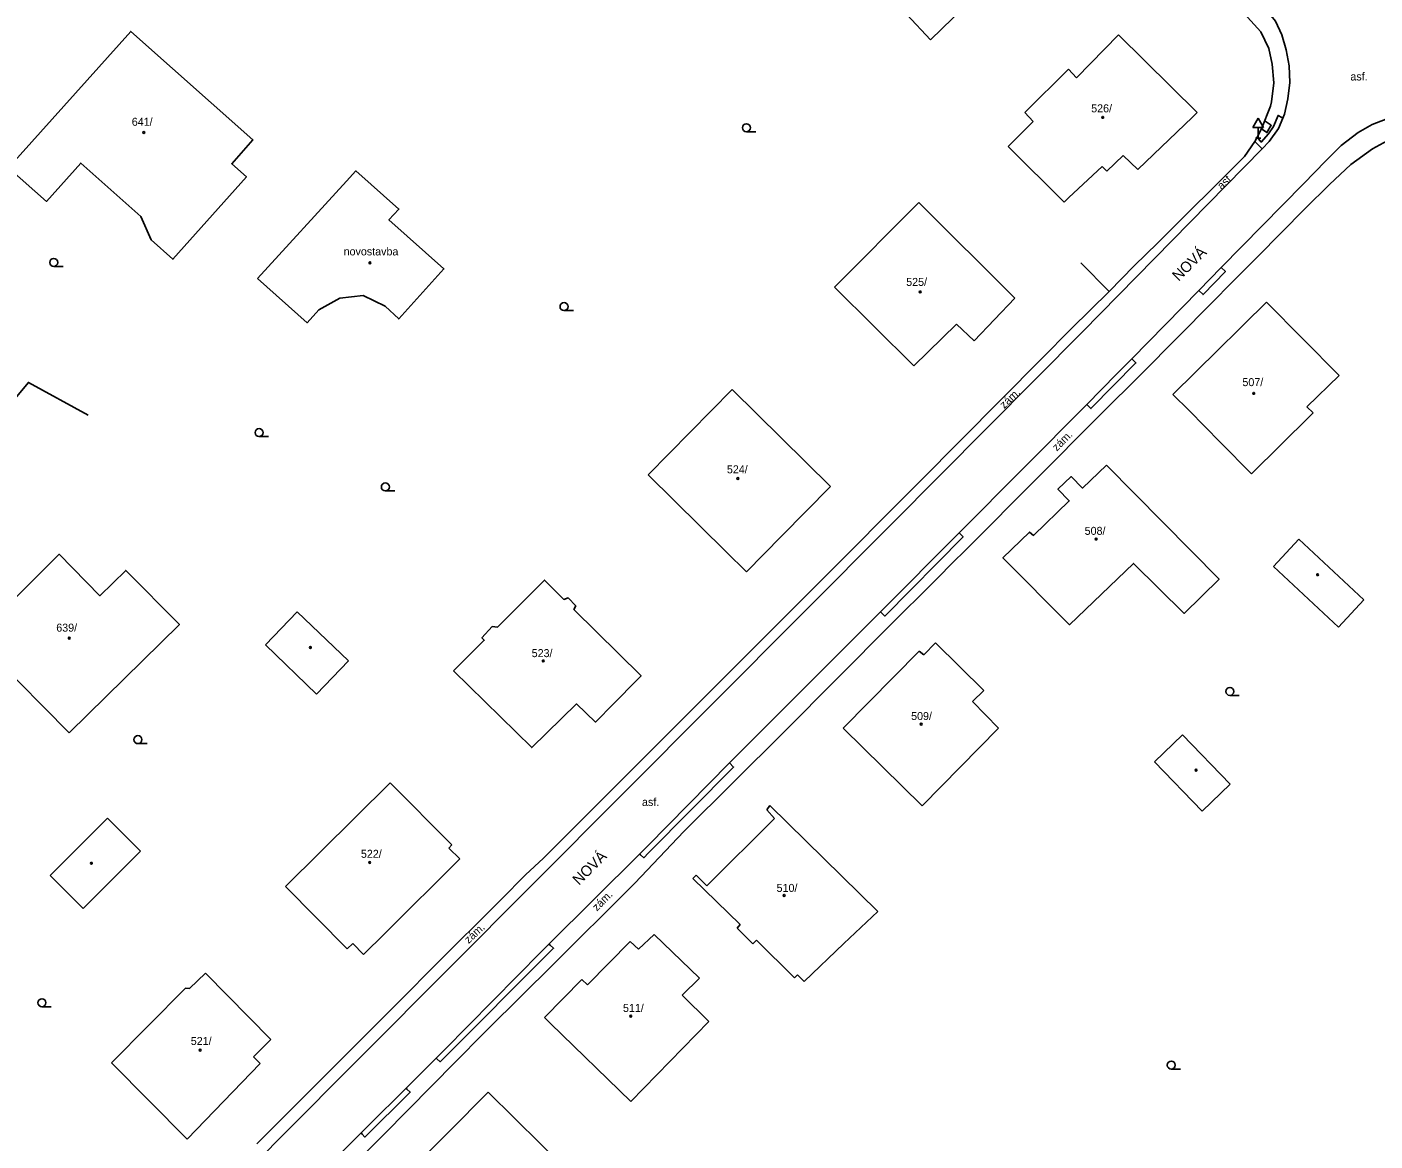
# Model space of a CAD drawing. Extents: x -737488 to -734267, y -1145775 to -1142573.
# Drawn here: x -736592 to -736465.6, y -1144304.9 to -1144200.4 of the extents above; entities that cross this region are included whole.
import ezdxf

# ---------------------------------------------------------------- set-up
doc = ezdxf.new("R2010")
doc.units = 0
for name, color, linetype in [('Vrstva 1', 7, 'Continuous'), ('Vrstva 10', 7, 'Continuous'), ('Vrstva 13', 7, 'Continuous'), ('Vrstva 14', 7, 'Continuous'), ('Vrstva 3', 7, 'Continuous'), ('Vrstva 4', 7, 'Continuous'), ('Vrstva 5', 7, 'Continuous'), ('Vrstva 6', 7, 'Continuous'), ('Vrstva 8', 7, 'Continuous'), ('Vrstva 9', 7, 'Continuous')]:
    doc.layers.add(name, color=color, linetype=linetype)

# ---------------------------------------------------------------- blocks, each defined once
blk = doc.blocks.new('3.040')
at = {"layer": 'Vrstva 1'}
blk.add_line((0, -0.75), (1.75, -0.75), dxfattribs=at)
blk.add_circle((0, 0), 0.75, dxfattribs=at)
blk = doc.blocks.new('4.020')
at = {"layer": 'Vrstva 1'}
blk.add_circle((0, 0), 0.175, dxfattribs=at)
blk = doc.blocks.new('5.270')
at = {"layer": 'Vrstva 1'}
for p, q in [((0, 3.732), (-1, 2)), ((0, 3.732), (1, 2)), ((-1, 2), (1, 2)), ((-0.5, 0), (0.5, 0)), ((0, 0), (0, 2))]:
    blk.add_line(p, q, dxfattribs=at)

msp = doc.modelspace()

# ---------------------------------------------------------------- linework, layer by layer
at = {"layer": 'Vrstva 10'}
for points in [[(-736569.58, -1144306.02), (-736568.51, -1144304.92), (-736544.53, -1144280.81), (-736510.86, -1144247.01), (-736493.03, -1144229.04), (-736476.18, -1144211.88), (-736475.51, -1144211.2), (-736474.66, -1144209.98), (-736474.24, -1144208.99), (-736474.08, -1144208.62), (-736473.78, -1144207.19), (-736473.58, -1144205.66), (-736473.65, -1144204.09), (-736473.93, -1144202.59), (-736474.33, -1144201.18), (-736474.93, -1144199.91), (-736475.73, -1144198.9), (-736476.44, -1144198.24), (-736477.53, -1144197.31), (-736478.84, -1144196.47), (-736482.87, -1144194.17)], [(-736463.99, -1144208.86), (-736465.87, -1144209.59), (-736467.18, -1144210.35), (-736468.78, -1144211.55), (-736470.21, -1144213), (-736472.3, -1144215.15), (-736480.01, -1144223.01), (-736482.11, -1144225.16), (-736488.4, -1144231.57), (-736489.82, -1144233), (-736492.62, -1144235.84), (-736504.6, -1144247.89), (-736511.95, -1144255.31), (-736526.13, -1144269.47), (-736533.8, -1144277.27), (-736534.56, -1144278.02), (-736543.04, -1144286.48), (-736543.73, -1144287.17), (-736552.87, -1144296.41), (-736553.61, -1144297.15), (-736556.44, -1144299.97), (-736559.96, -1144303.48), (-736560.66, -1144304.18), (-736564.18, -1144307.7)], [(-736476.66, -1144210.79), (-736476.26, -1144211.24), (-736475.57, -1144210.45), (-736475.13, -1144209.77), (-736474.69, -1144208.74), (-736474.34, -1144208.93), (-736474.24, -1144208.99)], [(-736475.9, -1144209.28), (-736475.33, -1144209.66), (-736475.73, -1144210.35), (-736476.24, -1144210.01)], [(-736476.86, -1144211.17), (-736476.27, -1144211.79), (-736476.18, -1144211.88)], [(-736482.11, -1144225.16), (-736481.72, -1144225.55), (-736479.62, -1144223.39), (-736480.01, -1144223.01)], [(-736492.62, -1144235.84), (-736492.23, -1144236.23), (-736488.01, -1144231.96), (-736488.4, -1144231.57)], [(-736592.95, -1144235.12), (-736591.84, -1144233.78), (-736586.24, -1144236.86)], [(-736511.95, -1144255.31), (-736511.56, -1144255.7), (-736504.21, -1144248.28), (-736504.6, -1144247.89)], [(-736534.56, -1144278.02), (-736534.47, -1144278.1), (-736534.16, -1144278.37), (-736533.72, -1144277.92), (-736525.74, -1144269.86), (-736526.13, -1144269.47)], [(-736553.61, -1144297.15), (-736553.54, -1144297.22), (-736553.24, -1144297.5), (-736542.61, -1144286.85), (-736542.93, -1144286.57), (-736543.04, -1144286.48)], [(-736560.66, -1144304.18), (-736560.54, -1144304.3), (-736560.29, -1144304.56), (-736556.05, -1144300.34), (-736556.35, -1144300.06), (-736556.44, -1144299.97)]]:
    msp.add_lwpolyline(points, dxfattribs=at)
at = {"layer": 'Vrstva 4'}
for points in [[(-736593.7, -1144213.67), (-736582.24, -1144200.86), (-736570.79, -1144211.03), (-736572.78, -1144213.27), (-736571.41, -1144214.51), (-736578.3, -1144222.23), (-736580.34, -1144220.41), (-736581.31, -1144218.21), (-736586.93, -1144213.21), (-736590.14, -1144216.81), (-736593.7, -1144213.67)], [(-736588.01, -1144266.66), (-736595.16, -1144259.45), (-736595, -1144255.91), (-736588.96, -1144249.9), (-736585.15, -1144253.79), (-736582.71, -1144251.42), (-736577.69, -1144256.48), (-736588.01, -1144266.66)]]:
    msp.add_lwpolyline(points, dxfattribs=at)
at = {"layer": 'Vrstva 5'}
for points in [[(-736499.97, -1144194.52), (-736507.28, -1144201.65)], [(-736507.28, -1144201.65), (-736509.5, -1144199.27)], [(-736493.6, -1144205.21), (-736489.64, -1144201.19)], [(-736489.64, -1144201.19), (-736482.28, -1144208.47)], [(-736498.44, -1144208.46), (-736494.34, -1144204.39)], [(-736494.34, -1144204.39), (-736493.6, -1144205.21)], [(-736497.65, -1144209.3), (-736498.44, -1144208.46)], [(-736482.72, -1144208.89), (-736487.83, -1144213.8)], [(-736482.28, -1144208.47), (-736482.72, -1144208.89)], [(-736499.99, -1144211.66), (-736497.65, -1144209.3)], [(-736494.73, -1144216.86), (-736499.99, -1144211.66)], [(-736489.22, -1144212.5), (-736490.75, -1144213.96)], [(-736487.83, -1144213.8), (-736489.22, -1144212.5)], [(-736570.37, -1144224.02), (-736562.03, -1144214.91), (-736561.16, -1144213.94), (-736557.1, -1144217.52), (-736558.04, -1144218.53), (-736552.89, -1144223.14), (-736557.13, -1144227.83), (-736558.41, -1144226.62), (-736560.46, -1144225.64), (-736562.65, -1144225.89), (-736564.6, -1144226.96), (-736565.71, -1144228.18), (-736570.37, -1144224.02)], [(-736491.19, -1144213.53), (-736494.29, -1144216.44)], [(-736490.75, -1144213.96), (-736491.19, -1144213.53)], [(-736494.29, -1144216.44), (-736494.73, -1144216.86)], [(-736516.26, -1144224.84), (-736508.37, -1144216.92)], [(-736508.37, -1144216.92), (-736499.37, -1144225.89)], [(-736508.84, -1144232.24), (-736516.26, -1144224.84)], [(-736499.37, -1144225.89), (-736503.18, -1144229.89)], [(-736475.78, -1144226.25), (-736477.91, -1144228.36)], [(-736468.97, -1144233.12), (-736475.78, -1144226.25)], [(-736504.82, -1144228.32), (-736508.84, -1144232.24)], [(-736503.18, -1144229.89), (-736504.82, -1144228.32)], [(-736478.37, -1144228.81), (-736480.26, -1144230.68)], [(-736477.91, -1144228.36), (-736478.37, -1144228.81)], [(-736480.26, -1144230.68), (-736484.54, -1144234.9)], [(-736472, -1144236.08), (-736468.97, -1144233.12)], [(-736533.75, -1144242.45), (-736525.86, -1144234.45)], [(-736525.86, -1144234.45), (-736516.64, -1144243.55)], [(-736484.54, -1144234.9), (-736483.03, -1144236.43)], [(-736483.03, -1144236.43), (-736480.08, -1144239.41)], [(-736471.39, -1144236.63), (-736472, -1144236.08)], [(-736471.69, -1144236.92), (-736471.39, -1144236.63)], [(-736477.18, -1144242.35), (-736471.69, -1144236.92)], [(-736480.08, -1144239.41), (-736477.18, -1144242.35)], [(-736490.77, -1144241.54), (-736480.22, -1144252.24), (-736483.48, -1144255.45), (-736488.25, -1144250.76), (-736494.24, -1144256.52), (-736500.49, -1144250.23), (-736497.99, -1144247.82), (-736497.63, -1144248.13), (-736494.27, -1144244.9), (-736495.32, -1144243.81), (-736494.09, -1144242.61), (-736493.03, -1144243.7), (-736490.77, -1144241.54)], [(-736526.44, -1144249.66), (-736533.75, -1144242.45)], [(-736516.64, -1144243.55), (-736521.23, -1144248.2)], [(-736521.23, -1144248.2), (-736524.53, -1144251.55)], [(-736475.13, -1144251.05), (-736472.74, -1144248.48)], [(-736472.74, -1144248.48), (-736466.64, -1144254.18)], [(-736524.53, -1144251.55), (-736526.44, -1144249.66)], [(-736469.03, -1144256.74), (-736475.13, -1144251.05)], [(-736552, -1144260.85), (-736544.66, -1144268.03), (-736540.46, -1144263.94), (-736538.69, -1144265.64), (-736538.31, -1144265.26), (-736537.33, -1144264.27), (-736534.41, -1144261.31), (-736540.7, -1144255.07), (-736540.53, -1144254.74), (-736541.25, -1144254), (-736541.64, -1144254.14), (-736543.46, -1144252.33), (-736547.87, -1144256.73), (-736548.35, -1144256.69), (-736549.32, -1144257.74), (-736549.11, -1144257.97), (-736552, -1144260.85)], [(-736466.64, -1144254.18), (-736469.03, -1144256.74)], [(-736566.64, -1144255.29), (-736569.63, -1144258.41)], [(-736561.83, -1144259.89), (-736566.64, -1144255.29)], [(-736569.63, -1144258.41), (-736564.82, -1144263.01)], [(-736508.32, -1144258.98), (-736515.45, -1144266.22)], [(-736507.91, -1144259.34), (-736508.32, -1144258.98)], [(-736506.81, -1144258.22), (-736507.91, -1144259.34)], [(-736502.27, -1144262.67), (-736506.81, -1144258.22)], [(-736564.82, -1144263.01), (-736561.83, -1144259.89)], [(-736503.35, -1144263.72), (-736502.27, -1144262.67)], [(-736500.9, -1144266.22), (-736503.35, -1144263.72)], [(-736515.45, -1144266.22), (-736508.04, -1144273.49)], [(-736508.04, -1144273.49), (-736500.9, -1144266.22)], [(-736483.64, -1144266.84), (-736486.26, -1144269.38)], [(-736479.17, -1144271.45), (-736483.64, -1144266.84)], [(-736486.26, -1144269.38), (-736481.79, -1144273.99)], [(-736567.74, -1144281.06), (-736557.92, -1144271.34)], [(-736557.92, -1144271.34), (-736552.14, -1144277.17)], [(-736481.79, -1144273.99), (-736479.17, -1144271.45)], [(-736522.33, -1144273.47), (-736522.63, -1144273.88)], [(-736522.63, -1144273.88), (-736521.91, -1144274.68)], [(-736512.2, -1144283.4), (-736522.33, -1144273.47)], [(-736589.81, -1144280.03), (-736584.44, -1144274.66)], [(-736584.44, -1144274.66), (-736581.34, -1144277.76)], [(-736521.91, -1144274.68), (-736528.25, -1144280.99)], [(-736581.34, -1144277.76), (-736586.71, -1144283.13)], [(-736552.14, -1144277.17), (-736552.44, -1144277.48)], [(-736552.44, -1144277.48), (-736551.39, -1144278.46)], [(-736551.39, -1144278.46), (-736558.42, -1144285.46)], [(-736586.71, -1144283.13), (-736589.81, -1144280.03)], [(-736529.24, -1144279.99), (-736529.54, -1144280.31)], [(-736529.54, -1144280.31), (-736525.12, -1144284.63)], [(-736528.25, -1144280.99), (-736529.24, -1144279.99)], [(-736561.97, -1144286.9), (-736567.74, -1144281.06)], [(-736515.4, -1144286.42), (-736512.2, -1144283.4)], [(-736525.12, -1144284.63), (-736525.41, -1144284.97)], [(-736558.42, -1144285.46), (-736560.42, -1144287.45)], [(-736534.66, -1144286.95), (-736533.18, -1144285.57)], [(-736533.18, -1144285.57), (-736528.94, -1144289.67)], [(-736525.41, -1144284.97), (-736523.92, -1144286.43)], [(-736561.43, -1144286.4), (-736561.97, -1144286.9)], [(-736560.42, -1144287.45), (-736561.43, -1144286.4)], [(-736539.42, -1144290.3), (-736535.43, -1144286.23)], [(-736535.43, -1144286.23), (-736534.66, -1144286.95)], [(-736523.92, -1144286.43), (-736523.6, -1144286.11)], [(-736523.6, -1144286.11), (-736520.02, -1144289.63)], [(-736519.11, -1144289.97), (-736515.4, -1144286.42)], [(-736575.24, -1144289.2), (-736576.75, -1144290.64)], [(-736569.1, -1144295.4), (-736575.24, -1144289.2)], [(-736543.46, -1144293.35), (-736539.97, -1144289.78)], [(-736539.97, -1144289.78), (-736539.42, -1144290.3)], [(-736528.94, -1144289.67), (-736530.54, -1144291.26)], [(-736520.02, -1144289.63), (-736519.73, -1144289.36)], [(-736519.73, -1144289.36), (-736519.11, -1144289.97)], [(-736577.13, -1144290.59), (-736584.06, -1144297.6)], [(-736576.75, -1144290.64), (-736577.13, -1144290.59)], [(-736530.54, -1144291.26), (-736528.06, -1144293.74)], [(-736542.89, -1144293.91), (-736543.46, -1144293.35)], [(-736535.37, -1144301.22), (-736542.89, -1144293.91)], [(-736528.06, -1144293.74), (-736535.37, -1144301.22)], [(-736570.73, -1144297.03), (-736569.1, -1144295.4)], [(-736570.1, -1144297.67), (-736570.73, -1144297.03)], [(-736584.06, -1144297.6), (-736576.97, -1144304.76)], [(-736576.97, -1144304.76), (-736570.1, -1144297.67)], [(-736556.07, -1144307.75), (-736548.75, -1144300.35)], [(-736548.75, -1144300.35), (-736541.34, -1144307.68)]]:
    msp.add_lwpolyline(points, dxfattribs=at)
at = {"layer": 'Vrstva 9'}
for points in [[(-736475.23, -1144203.94), (-736475.55, -1144202.47), (-736476.29, -1144200.91), (-736477.55, -1144199.53), (-736478.22, -1144198.88), (-736479.58, -1144198.09)], [(-736477.82, -1144212.6), (-736476.86, -1144211.17), (-736476.66, -1144210.79), (-736476.24, -1144210.01), (-736475.41, -1144207.88), (-736475.3, -1144207.46), (-736475.1, -1144205.68), (-736475.23, -1144203.94)], [(-736461.57, -1144210.4), (-736462.9, -1144210.65), (-736464.47, -1144211.12), (-736465.82, -1144211.88), (-736467.87, -1144213.34)], [(-736485.96, -1144220.7), (-736477.82, -1144212.6)], [(-736467.87, -1144213.34), (-736469.88, -1144215.21)], [(-736469.88, -1144215.21), (-736472.15, -1144217.48)], [(-736472.15, -1144217.48), (-736476.62, -1144222.01)], [(-736485.96, -1144220.7), (-736488.17, -1144222.85)], [(-736493.17, -1144222.56), (-736490.52, -1144225.24)], [(-736476.62, -1144222.01), (-736479.04, -1144224.45)], [(-736490.52, -1144225.24), (-736488.17, -1144222.85)], [(-736494.04, -1144228.72), (-736490.52, -1144225.24)], [(-736479.04, -1144224.45), (-736480.83, -1144226.27)], [(-736480.83, -1144226.27), (-736487.47, -1144232.95)], [(-736494.04, -1144228.72), (-736496.9, -1144231.61)], [(-736508.2, -1144243), (-736496.9, -1144231.61)], [(-736487.47, -1144232.95), (-736491.41, -1144236.85)], [(-736491.41, -1144236.85), (-736503.66, -1144249.17)], [(-736511.6, -1144246.39), (-736508.2, -1144243)], [(-736511.6, -1144246.39), (-736514.51, -1144249.35)], [(-736525.87, -1144260.71), (-736514.51, -1144249.35)], [(-736503.66, -1144249.17), (-736505.54, -1144251.04)], [(-736506.24, -1144251.76), (-736507.08, -1144252.6)], [(-736505.54, -1144251.04), (-736506.24, -1144251.76)], [(-736507.08, -1144252.6), (-736510.92, -1144256.42)], [(-736510.92, -1144256.42), (-736521.04, -1144266.63)], [(-736528.82, -1144263.69), (-736525.87, -1144260.71)], [(-736528.82, -1144263.69), (-736532.15, -1144266.99)], [(-736543.55, -1144278.4), (-736532.15, -1144266.99)], [(-736521.04, -1144266.63), (-736530.39, -1144275.91)], [(-736530.39, -1144275.91), (-736535, -1144280.76)], [(-736543.55, -1144278.4), (-736545.24, -1144279.98)], [(-736545.24, -1144279.98), (-736547.53, -1144282.27)], [(-736535, -1144280.76), (-736543.02, -1144288.75)], [(-736553.86, -1144288.59), (-736547.53, -1144282.27)], [(-736553.86, -1144288.59), (-736556.72, -1144291.49)], [(-736543.02, -1144288.75), (-736545.27, -1144290.99)], [(-736545.27, -1144290.99), (-736549.15, -1144294.83)], [(-736561.27, -1144296.03), (-736556.72, -1144291.49)], [(-736549.15, -1144294.83), (-736551.79, -1144297.52)], [(-736570.44, -1144305.2), (-736561.27, -1144296.03)], [(-736551.79, -1144297.52), (-736556.26, -1144302.03)], [(-736556.26, -1144302.03), (-736558.51, -1144304.31)], [(-736558.51, -1144304.31), (-736563.14, -1144308.96)]]:
    msp.add_lwpolyline(points, dxfattribs=at)

# ---------------------------------------------------------------- block references
at = {"layer": 'Vrstva 3', "xscale": 0.5, "yscale": 0.5}
for p in [(-736524.53, -1144209.89), (-736589.47, -1144222.53), (-736541.63, -1144226.67), (-736570.22, -1144238.49), (-736558.38, -1144243.59), (-736479.21, -1144262.77), (-736581.57, -1144267.29), (-736590.57, -1144291.97), (-736484.7, -1144297.82)]:
    msp.add_blockref('3.040', p, dxfattribs=at)
at = {"layer": 'Vrstva 8', "xscale": 0.5, "yscale": 0.5}
for p in [(-736491.13, -1144208.92), (-736581.03, -1144210.34), (-736559.82, -1144222.57), (-736508.24, -1144225.3), (-736476.97, -1144234.81), (-736525.33, -1144242.8), (-736491.75, -1144248.47), (-736470.98, -1144251.82), (-736588.01, -1144257.77), (-736565.41, -1144258.64), (-736543.57, -1144259.91), (-736508.14, -1144265.83), (-736482.38, -1144270.16), (-736585.94, -1144278.89), (-736559.85, -1144278.81), (-736521, -1144281.9), (-736535.38, -1144293.23), (-736575.74, -1144296.41)]:
    msp.add_blockref('4.020', p, dxfattribs=at)
at = {"layer": 'Vrstva 9', "xscale": 0.5, "yscale": 0.5}
msp.add_blockref('5.270', (-736476.55, -1144210.86), dxfattribs=at)

# ---------------------------------------------------------------- texts
at = {"layer": 'Vrstva 13'}
for p in [(-736484.01, -1144224.34), (-736540.23, -1144280.99)]:
    msp.add_text('NOVÁ', height=1, rotation=44.716, dxfattribs=at).set_placement(p)
at = {"layer": 'Vrstva 14'}
for s, p in [('asf.', (-736467.91, -1144205.46)), ('novostavba', (-736562.29, -1144221.87)), ('asf.', (-736534.32, -1144273.51))]:
    msp.add_text(s, height=0.75, dxfattribs=at).set_placement(p)
for s, rotation, p in [('asf.', 43.038, (-736479.98, -1144215.75)), ('zám.', 43.038, (-736500.37, -1144236.29)), ('zám.', 44.933, (-736495.43, -1144240.28)), ('zám.', 44.933, (-736538.54, -1144283.42)), ('zám.', 43.038, (-736550.57, -1144286.46))]:
    msp.add_text(s, height=0.75, rotation=rotation, dxfattribs=at).set_placement(p)
at = {"layer": 'Vrstva 6'}
for s, p in [('526/', (-736492.21, -1144208.45)), ('641/', (-736582.15, -1144209.71)), ('525/', (-736509.55, -1144224.73)), ('507/', (-736478.03, -1144234.13)), ('524/', (-736526.36, -1144242.31)), ('508/', (-736492.82, -1144248.08)), ('639/', (-736589.23, -1144257.16)), ('523/', (-736544.66, -1144259.55)), ('509/', (-736509.09, -1144265.45)), ('522/', (-736560.67, -1144278.37)), ('510/', (-736521.7, -1144281.57)), ('511/', (-736536.1, -1144292.83)), ('521/', (-736576.62, -1144295.93))]:
    msp.add_text(s, height=0.75, dxfattribs=at).set_placement(p)

doc.saveas('drawing.dxf')
